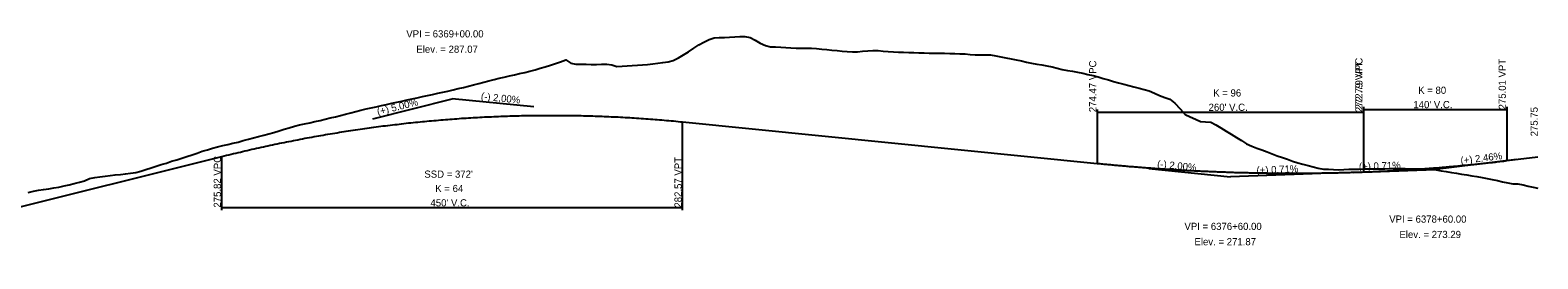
# Model space of a CAD drawing. Extents: x 1838386 to 1955906, y 719739 to 834437.
# Drawn here: x 1952044 to 1953517, y 768718 to 768942 of the extents above; entities that cross this region are included whole.
import ezdxf

# ---------------------------------------------------------------- set-up
doc = ezdxf.new("R2010")
doc.units = 0
for name, color, linetype in [('RD_DDB_GradeTX', 7, 'Continuous'), ('RD_DDB_Profile_EX', 7, 'Continuous'), ('RD_DDB_Profile_Lbl', 7, 'Continuous'), ('RD_DDB_Profile_PR', 7, 'Continuous'), ('RD_DDB_StripGrade', 7, 'Continuous'), ('RD_DDB_VCLbl', 7, 'Continuous')]:
    doc.layers.add(name, color=color, linetype=linetype)

msp = doc.modelspace()

# ---------------------------------------------------------------- linework, layer by layer
at = {"layer": 'RD_DDB_GradeTX'}
for p, q in [((1952378.8, 768855.1), (1952456.4, 768874.5)), ((1952536, 768866.6), (1952456.4, 768874.5)), ((1953136.8, 768806.5), (1953216.4, 768798.5)), ((1953336.4, 768802.7), (1953416.4, 768805.6)), ((1953495.8, 768815.3), (1953416.4, 768805.6)), ((1953296.3, 768801.3), (1953216.4, 768798.5))]:
    msp.add_line(p, q, dxfattribs=at)
at = {"layer": 'RD_DDB_Profile_EX'}
for points in [[(1952417.2, 768874.5), (1952422.2, 768875.6), (1952427.2, 768876.7), (1952432.2, 768877.8), (1952437.2, 768878.9), (1952442.2, 768880.1), (1952447.2, 768881.1), (1952452.2, 768882.1), (1952457.2, 768883.3), (1952462.2, 768884.5), (1952467.2, 768885.7), (1952472.2, 768886.9), (1952477.2, 768888.2), (1952482.2, 768889.5), (1952487.2, 768890.9), (1952492.2, 768892.1), (1952497.2, 768893.4), (1952502.2, 768894.7), (1952507.2, 768895.8), (1952512.2, 768897), (1952517.2, 768898.1), (1952522.2, 768899.2), (1952527.2, 768900.3), (1952532.2, 768901.6), (1952537.2, 768903), (1952542.2, 768904.4), (1952547.2, 768905.9), (1952552.2, 768907.4), (1952557.2, 768909.1), (1952562.2, 768910.8), (1952567.2, 768912.5), (1952572.2, 768909.4), (1952577.2, 768908.4), (1952582.2, 768908.3), (1952587.2, 768908.3), (1952592.2, 768908.2), (1952597.2, 768908.2), (1952602.2, 768908.3), (1952607.2, 768908.4), (1952612.2, 768907.6), (1952617.2, 768906.2), (1952622.2, 768906.4), (1952627.2, 768906.7), (1952632.2, 768907), (1952637.2, 768907.3), (1952642.2, 768907.8), (1952647.2, 768908.2), (1952652.2, 768908.8), (1952657.2, 768909.4), (1952662.2, 768910.1), (1952667.2, 768910.7), (1952672.2, 768911.9), (1952677.2, 768914.6), (1952682.2, 768917.6), (1952687.2, 768920.4), (1952692.2, 768924.1), (1952697.2, 768927.4), (1952702.2, 768930), (1952707.2, 768932.6), (1952712.2, 768934), (1952717.2, 768934.3), (1952722.2, 768934.6), (1952727.2, 768934.9), (1952732.2, 768935.1), (1952737.2, 768935.3), (1952742.2, 768935.5), (1952747.2, 768934.6), (1952752.2, 768931.8), (1952757.2, 768928.9), (1952762.2, 768926.6), (1952767.2, 768925.4), (1952772.2, 768925.2), (1952777.2, 768925), (1952782.2, 768924.6), (1952787.2, 768924.3), (1952792.2, 768924.1), (1952797.2, 768924.1), (1952802.2, 768924.1), (1952807.2, 768924.1), (1952812.2, 768923.7), (1952817.2, 768923.2), (1952822.2, 768922.6), (1952827.2, 768922.1), (1952832.2, 768921.6), (1952837.2, 768921.2), (1952842.2, 768920.8), (1952847.2, 768920.5), (1952852.2, 768920.6), (1952857.2, 768921), (1952862.2, 768921.3), (1952867.2, 768921.6), (1952872.2, 768921.6), (1952877.2, 768921.2), (1952882.2, 768920.7), (1952887.2, 768920.4), (1952892.2, 768920.2), (1952897.2, 768920.1), (1952902.2, 768919.9), (1952907.2, 768919.7), (1952912.2, 768919.6), (1952917.2, 768919.4)], [(1952917.2, 768919.4), (1952922.2, 768919.3), (1952927.2, 768919.3), (1952932.2, 768919.2), (1952937.2, 768919), (1952942.2, 768918.9), (1952947.2, 768918.7), (1952952.2, 768918.6), (1952957.2, 768918.5), (1952962.2, 768917.8), (1952967.2, 768917.5), (1952972.2, 768917.5), (1952977.2, 768917.4), (1952982.2, 768917.4), (1952987.2, 768916.5), (1952992.2, 768915.5), (1952997.2, 768914.5), (1953002.2, 768913.5), (1953007.2, 768912.5), (1953012.2, 768911.5), (1953017.2, 768910.5), (1953022.2, 768909.5), (1953027.2, 768908.5), (1953032.2, 768907.6), (1953037.2, 768906.7), (1953042.2, 768905.7), (1953047.2, 768904.5), (1953052.2, 768903.2), (1953057.2, 768902.3), (1953062.2, 768901.5), (1953067.2, 768900.7), (1953072.2, 768899.6), (1953077.2, 768898.4), (1953082.2, 768897.2), (1953087.2, 768895.9), (1953092.2, 768894.5), (1953097.2, 768893.1), (1953102.2, 768891.4), (1953107.2, 768890.1), (1953112.2, 768888.8), (1953117.2, 768887.5), (1953122.2, 768886.2), (1953127.2, 768884.9), (1953132.2, 768883.6), (1953137.2, 768882.2), (1953142.2, 768880.2), (1953147.2, 768877.9), (1953152.2, 768875.7), (1953157.2, 768874.2), (1953162.2, 768870.3), (1953167.2, 768864.7), (1953172.2, 768859.4), (1953177.2, 768857), (1953182.2, 768854.8), (1953187.2, 768852.5), (1953192.2, 768852), (1953197.2, 768851.6), (1953202.2, 768849.2), (1953207.2, 768846.1), (1953212.2, 768843), (1953217.2, 768839.9), (1953222.2, 768836.9), (1953227.2, 768833.8), (1953232.2, 768830.7), (1953237.2, 768828.4), (1953242.2, 768826.5), (1953247.2, 768824.6), (1953252.2, 768822.7), (1953257.2, 768820.8), (1953262.2, 768818.9), (1953267.2, 768817.2), (1953272.2, 768815.5), (1953277.2, 768813.8), (1953282.2, 768812.1), (1953287.2, 768810.7), (1953292.2, 768809.4), (1953297.2, 768808.1), (1953302.2, 768806.8), (1953307.2, 768805.9), (1953312.2, 768805.7), (1953317.2, 768805.4), (1953322.2, 768805.3), (1953327.2, 768805.5), (1953332.2, 768805.7), (1953337.2, 768805.9), (1953342.2, 768806), (1953347.2, 768806.2), (1953352.2, 768806.2), (1953357.2, 768806.3), (1953362.2, 768806.3), (1953367.2, 768806.3), (1953372.2, 768806.4), (1953377.2, 768806.4), (1953382.2, 768806.4), (1953387.2, 768806.4), (1953392.2, 768806.3), (1953397.2, 768806.3), (1953402.2, 768806.1), (1953407.2, 768805.9), (1953412.2, 768805.7), (1953417.2, 768805.1)], [(1952042.2, 768783.2), (1952047.2, 768784.3), (1952052.2, 768785.2), (1952057.2, 768786), (1952062.2, 768786.7), (1952067.2, 768787.5), (1952072.2, 768788.3), (1952077.2, 768789.5), (1952082.2, 768790.7), (1952087.2, 768792), (1952092.2, 768793.2), (1952097.2, 768794.6), (1952102.2, 768796.6), (1952107.2, 768797.7), (1952112.2, 768798.3), (1952117.2, 768798.9), (1952122.2, 768799.5), (1952127.2, 768800.2), (1952132.2, 768800.7), (1952137.2, 768801.4), (1952142.2, 768802), (1952147.2, 768802.6), (1952152.2, 768803.9), (1952157.2, 768805.5), (1952162.2, 768807.1), (1952167.2, 768808.7), (1952172.2, 768810.3), (1952177.2, 768811.8), (1952182.2, 768813.5), (1952187.2, 768815.1), (1952192.2, 768816.7), (1952197.2, 768818.3), (1952202.2, 768819.9), (1952207.2, 768821.6), (1952212.2, 768823.3), (1952217.2, 768824.8), (1952222.2, 768826.2), (1952227.2, 768827.6), (1952232.2, 768829), (1952237.2, 768830.1), (1952242.2, 768831.2), (1952247.2, 768832.3), (1952252.2, 768833.8), (1952257.2, 768835.3), (1952262.2, 768836.6), (1952267.2, 768837.9), (1952272.2, 768839.1), (1952277.2, 768840.4), (1952282.2, 768841.8), (1952287.2, 768843.3), (1952292.2, 768844.8), (1952297.2, 768846.3), (1952302.2, 768847.8), (1952307.2, 768849), (1952312.2, 768850.1), (1952317.2, 768851.2), (1952322.2, 768852.3), (1952327.2, 768853.4), (1952332.2, 768854.6), (1952337.2, 768855.9), (1952342.2, 768857), (1952347.2, 768858.2), (1952352.2, 768859.5), (1952357.2, 768860.8), (1952362.2, 768862.1), (1952367.2, 768863.5), (1952372.2, 768864.8), (1952377.2, 768865.8), (1952382.2, 768866.8), (1952387.2, 768867.9), (1952392.2, 768869), (1952397.2, 768870.2), (1952402.2, 768871.3), (1952407.2, 768872.4), (1952412.2, 768873.4), (1952417.2, 768874.5)], [(1953417.2, 768805.1), (1953422.2, 768804.3), (1953427.2, 768803.5), (1953432.2, 768802.7), (1953437.2, 768801.9), (1953442.2, 768801.1), (1953447.2, 768800.3), (1953452.2, 768799.4), (1953457.2, 768798.6), (1953462.2, 768797.7), (1953467.2, 768796.8), (1953472.2, 768795.8), (1953477.2, 768794.7), (1953482.2, 768793.6), (1953487.2, 768792.5), (1953492.2, 768791.6), (1953497.2, 768791.4), (1953502.2, 768790.4), (1953507.2, 768789.3), (1953512.2, 768788.2), (1953516.6, 768787.3)]]:
    msp.add_lwpolyline(points, dxfattribs=at)
at = {"layer": 'RD_DDB_Profile_PR'}
for p, q in [((1952681.4, 768852), (1953086.4, 768811.5)), ((1951831.4, 768718.3), (1952231.4, 768818.3)), ((1953486.4, 768814.2), (1953516.6, 768817.9))]:
    msp.add_line(p, q, dxfattribs=at)
for points in [[(1952231.4, 768818.3), (1952240.4, 768820.5), (1952249.4, 768822.6), (1952258.4, 768824.7), (1952267.4, 768826.8), (1952276.4, 768828.7), (1952285.4, 768830.6), (1952294.4, 768832.5), (1952303.4, 768834.2), (1952312.4, 768836), (1952321.4, 768837.6), (1952330.4, 768839.2), (1952339.4, 768840.7), (1952348.4, 768842.2), (1952357.4, 768843.6), (1952366.4, 768844.9), (1952375.4, 768846.2), (1952384.4, 768847.4), (1952393.4, 768848.6), (1952402.4, 768849.6), (1952411.4, 768850.7), (1952420.4, 768851.6), (1952429.4, 768852.5), (1952438.4, 768853.3), (1952447.4, 768854.1), (1952456.4, 768854.8), (1952465.4, 768855.5), (1952474.4, 768856), (1952483.4, 768856.6), (1952492.4, 768857), (1952501.4, 768857.4), (1952510.4, 768857.7), (1952519.4, 768858), (1952528.4, 768858.2), (1952537.4, 768858.3), (1952546.4, 768858.4), (1952555.4, 768858.4), (1952564.4, 768858.4), (1952573.4, 768858.3), (1952582.4, 768858.1), (1952591.4, 768857.9), (1952600.4, 768857.6), (1952609.4, 768857.2), (1952618.4, 768856.8), (1952627.4, 768856.3), (1952636.4, 768855.7), (1952645.4, 768855.1), (1952654.4, 768854.4), (1952663.4, 768853.7), (1952672.4, 768852.9), (1952681.4, 768852)], [(1953086.4, 768811.5), (1953091.6, 768811), (1953096.8, 768810.5), (1953102, 768810), (1953107.2, 768809.5), (1953112.4, 768809.1), (1953117.6, 768808.6), (1953122.8, 768808.2), (1953128, 768807.8), (1953133.2, 768807.4), (1953138.4, 768807), (1953143.6, 768806.6), (1953148.8, 768806.3), (1953154, 768805.9), (1953159.2, 768805.6), (1953164.4, 768805.3), (1953169.6, 768805), (1953174.8, 768804.7), (1953180, 768804.4), (1953185.2, 768804.2), (1953190.4, 768803.9), (1953195.6, 768803.7), (1953200.8, 768803.5), (1953206, 768803.3), (1953211.2, 768803.1), (1953216.4, 768802.9), (1953221.6, 768802.7), (1953226.8, 768802.6), (1953232, 768802.5), (1953237.2, 768802.3), (1953242.4, 768802.2), (1953247.6, 768802.2), (1953252.8, 768802.1), (1953258, 768802), (1953263.2, 768802), (1953268.4, 768801.9), (1953273.6, 768801.9), (1953278.8, 768801.9), (1953284, 768801.9), (1953289.2, 768801.9), (1953294.4, 768802), (1953299.6, 768802), (1953304.8, 768802.1), (1953310, 768802.2), (1953315.2, 768802.3), (1953320.4, 768802.4), (1953325.6, 768802.5), (1953330.8, 768802.6), (1953336, 768802.8), (1953341.2, 768802.9), (1953346.4, 768803.1)], [(1953346.4, 768803.1), (1953349.2, 768803.2), (1953352, 768803.3), (1953354.8, 768803.4), (1953357.6, 768803.5), (1953360.4, 768803.7), (1953363.2, 768803.8), (1953366, 768803.9), (1953368.8, 768804), (1953371.6, 768804.2), (1953374.4, 768804.3), (1953377.2, 768804.5), (1953380, 768804.6), (1953382.8, 768804.8), (1953385.6, 768805), (1953388.4, 768805.1), (1953391.2, 768805.3), (1953394, 768805.5), (1953396.8, 768805.7), (1953399.6, 768805.9), (1953402.4, 768806.1), (1953405.2, 768806.3), (1953408, 768806.5), (1953410.8, 768806.7), (1953413.6, 768806.9), (1953416.4, 768807.1), (1953419.2, 768807.3), (1953422, 768807.6), (1953424.8, 768807.8), (1953427.6, 768808), (1953430.4, 768808.3), (1953433.2, 768808.5), (1953436, 768808.8), (1953438.8, 768809), (1953441.6, 768809.3), (1953444.4, 768809.6), (1953447.2, 768809.8), (1953450, 768810.1), (1953452.8, 768810.4), (1953455.6, 768810.7), (1953458.4, 768811), (1953461.2, 768811.3), (1953464, 768811.6), (1953466.8, 768811.9), (1953469.6, 768812.2), (1953472.4, 768812.5), (1953475.2, 768812.8), (1953478, 768813.2), (1953480.8, 768813.5), (1953483.6, 768813.8), (1953486.4, 768814.2)]]:
    msp.add_spline(points, degree=3, dxfattribs=at)
at = {"layer": 'RD_DDB_VCLbl'}
for p, q in [((1953086.4, 768864), (1953086.4, 768811.5)), ((1953346.4, 768866.7), (1953346.4, 768803.1)), ((1953346.4, 768864.2), (1953486.4, 768864.2)), ((1953346.4, 768864), (1953346.4, 768803.1)), ((1953486.4, 768866.7), (1953486.4, 768814.2)), ((1952681.4, 768765.8), (1952681.4, 768852)), ((1953086.4, 768861.5), (1953346.4, 768861.5)), ((1952231.4, 768765.8), (1952231.4, 768818.3)), ((1952231.4, 768768.3), (1952681.4, 768768.3))]:
    msp.add_line(p, q, dxfattribs=at)

# ---------------------------------------------------------------- texts
at = {"layer": 'RD_DDB_GradeTX'}
for s, rotation, p in [('(-) 2.00%', 354.2894, (1952484.1, 768873.7)), ('(+) 5.00%', 14.0362, (1952383.8, 768858.4)), ('(+) 2.46%', 7.0122, (1953441.6, 768810.7)), ('(-) 2.00%', 354.2894, (1953144.6, 768807.7)), ('(+) 0.71%', 2.0211, (1953242, 768801.4)), ('(+) 0.71%', 2.0211, (1953342, 768804.9))]:
    msp.add_text(s, height=7, rotation=rotation, dxfattribs=at).set_placement(p)
at = {"layer": 'RD_DDB_Profile_Lbl'}
for s, p in [('VPI = 6369+00.00', (1952411.5, 768934.5)), ('Elev. = 287.07', (1952421.3, 768919.5)), ('VPI = 6378+60.00', (1953371.5, 768753.6)), ('VPI = 6376+60.00', (1953171.5, 768746.5)), ('Elev. = 273.29', (1953381.5, 768738.6)), ('Elev. = 271.87', (1953181.3, 768731.5))]:
    msp.add_text(s, height=7, dxfattribs=at).set_placement(p)
msp.add_text('275.75', height=7, rotation=90, dxfattribs=at).set_placement((1953516.6, 768837.9))
at = {"layer": 'RD_DDB_StripGrade'}
for s, p in [('274.47 VPC', (1953085.4, 768861.5)), ('272.79 VPC', (1953345.4, 768864.2)), ('272.79 VPT', (1953345.4, 768861.5)), ('275.01 VPT', (1953485.4, 768864.2)), ('275.82 VPC', (1952230.4, 768768.3)), ('282.57 VPT', (1952680.4, 768768.3))]:
    msp.add_text(s, height=7, rotation=90, dxfattribs=at).set_placement(p)
at = {"layer": 'RD_DDB_VCLbl'}
for s, p in [('K = 96', (1953199.6, 768876.8)), ('K = 80', (1953399.8, 768879.4)), ("260' V.C.", (1953195.1, 768862.8)), ("140' V.C.", (1953395.1, 768865.4)), ("SSD = 372'", (1952429.1, 768797.5)), ('K = 64', (1952439.8, 768783.5)), ("450' V.C.", (1952435.1, 768769.5))]:
    msp.add_text(s, height=7, dxfattribs=at).set_placement(p)

doc.saveas('drawing.dxf')
